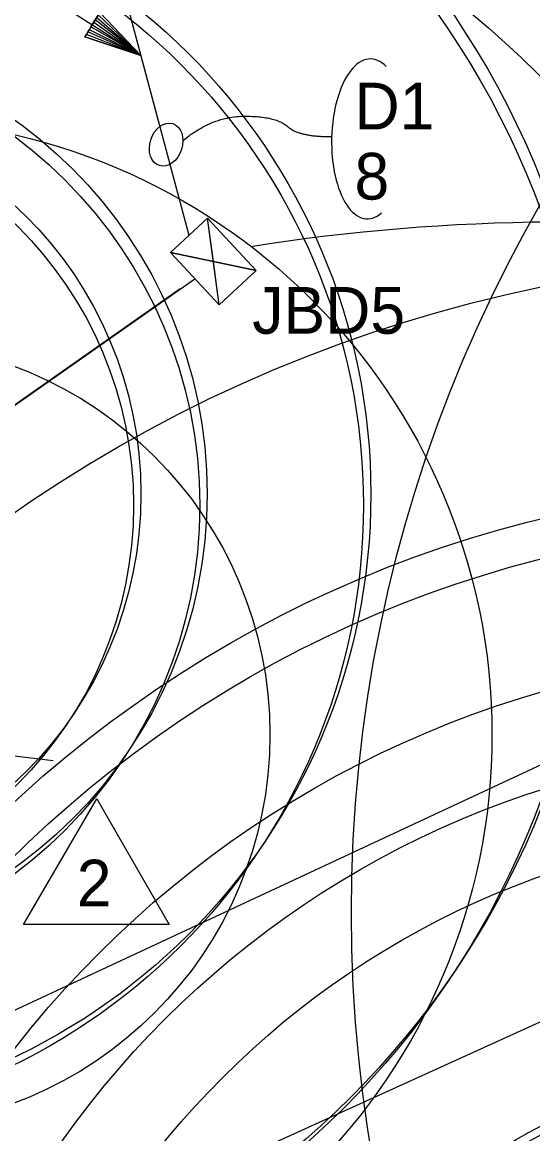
# Model space of a CAD drawing. Extents: x 1638506 to 1658005, y 834807 to 846788.
# Drawn here: x 1641089.4 to 1641220.4, y 842413 to 842698.3 of the extents above; entities that cross this region are included whole.
import ezdxf

# ---------------------------------------------------------------- set-up
doc = ezdxf.new("R2010")
doc.units = 0
for name, color, linetype in [('Default', 7, 'Continuous'), ('Old_Level_1', 7, 'Continuous'), ('Old_Level_2', 7, 'Continuous'), ('Old_Level_4', 7, 'Continuous'), ('Scratch_Level_0', 7, 'Continuous')]:
    doc.layers.add(name, color=color, linetype=linetype)

msp = doc.modelspace()

# ---------------------------------------------------------------- linework, layer by layer
at = {"layer": 'Default'}
for p, q in [((1640714.3, 842946.43), (1641119.83, 842689.85)), ((1641132.18, 842643.62), (1641110.09, 842726.34)), ((1641124.25, 842673.32), (1641111.22, 842722.11)), ((1641139.88, 842625.81), (1641136.93, 842648.03)), ((1641149.38, 842634.63), (1641127.43, 842639.21)), ((1641026.67, 842557.47), (1641133.66, 842632.51)), ((1641046.57, 842571.52), (1641129.92, 842630)), ((1641036.48, 842420.97), (1641307.23, 842547.27)), ((1641040.34, 842359.02), (1641350.44, 842500.06))]:
    msp.add_line(p, q, dxfattribs=at)
msp.add_lwpolyline([(1641107.33, 842697.76), (1641107.72, 842698.39), (1641119.83, 842689.85), (1641108.09, 842698.97), (1641108.49, 842699.59), (1641119.83, 842689.85), (1641108.88, 842700.22), (1641109.28, 842700.85), (1641119.83, 842689.85), (1641105.39, 842694.61), (1641105.75, 842695.26), (1641119.83, 842689.85), (1641106.18, 842695.86), (1641106.54, 842696.51), (1641119.83, 842689.85), (1641106.93, 842697.14), (1641109.28, 842700.85), (1641105.39, 842694.61), (1641119.83, 842689.85), (1641109.28, 842700.85)], dxfattribs=at)
for points in [[(1641139.88, 842625.81), (1641127.43, 842639.21), (1641136.93, 842648.03), (1641149.38, 842634.63)], [(1641138.41, 842636.92), (1641136.93, 842648.03), (1641127.43, 842639.21)], [(1641138.41, 842636.92), (1641149.38, 842634.63), (1641139.88, 842625.81)], [(1641127.04, 842466.75), (1641089.66, 842466.75), (1641108.48, 842499.01)]]:
    msp.add_lwpolyline(points, close=True, dxfattribs=at)
for start_param, end_param in [(2.710831, 4.712389), (4.712389, 6.681485)]:
    msp.add_ellipse((1641178.33, 842668.41), major_axis=(-0.49, -20.52), ratio=0.466223, start_param=start_param, end_param=end_param, dxfattribs=at)
msp.add_ellipse((1641126.29, 842666.93), major_axis=(1.72, 5.4), ratio=0.730797, dxfattribs=at)
msp.add_open_spline([(1641130.6, 842667.96), (1641138.17, 842674.23), (1641154.6, 842674.23), (1641160.28, 842668.94), (1641168.77, 842668.98)], degree=2, dxfattribs=at)
at = {"layer": 'Old_Level_1'}
for centre, radius in [((1641016.92, 842574.38), 297), ((1641016.92, 842574.38), 264), ((1641016.92, 842574.38), 219), ((1641016.92, 842574.38), 160), ((1641016.92, 842574.38), 118), ((1641016.92, 842574.38), 101), ((1641295.68, 842272.71), 365), ((1641295.68, 842272.71), 307), ((1641295.68, 842272.71), 240), ((1641295.68, 842272.71), 158)]:
    msp.add_circle(centre, radius, dxfattribs=at)
at = {"layer": 'Old_Level_2'}
msp.add_line((1641030.15, 842516.99), (1641097.33, 842508.79), dxfattribs=at)
msp.add_arc((1641228.74, 842129.06), 518, 64.8381, 98.9679, dxfattribs=at)
at = {"layer": 'Old_Level_4'}
for centre, radius in [((1641051.91, 842515.45), 365), ((1641538.84, 842469.72), 365), ((1641051.91, 842515.45), 307), ((1641051.91, 842515.45), 240), ((1641051.91, 842515.45), 158), ((1641051.91, 842515.45), 101)]:
    msp.add_circle(centre, radius, dxfattribs=at)
at = {"layer": 'Scratch_Level_0'}
for centre, radius in [((1641018.82, 842577.25), 297), ((1641018.82, 842577.25), 264), ((1641018.82, 842577.25), 219), ((1641018.82, 842577.25), 160), ((1641018.82, 842577.25), 118), ((1641018.82, 842577.25), 101), ((1641295.75, 842272.71), 297), ((1641295.75, 842272.71), 264), ((1641295.75, 842272.71), 219), ((1641295.75, 842272.71), 160)]:
    msp.add_circle(centre, radius, dxfattribs=at)

# ---------------------------------------------------------------- texts
at = {"layer": 'Default'}
for s, p in [('D1', (1641174.62, 842670.82)), ('8', (1641174.62, 842652.82)), ('JBD5', (1641148.38, 842618.38)), ('2', (1641103.35, 842471.35))]:
    msp.add_text(s, height=12, dxfattribs=at).set_placement(p)

doc.saveas('drawing.dxf')
